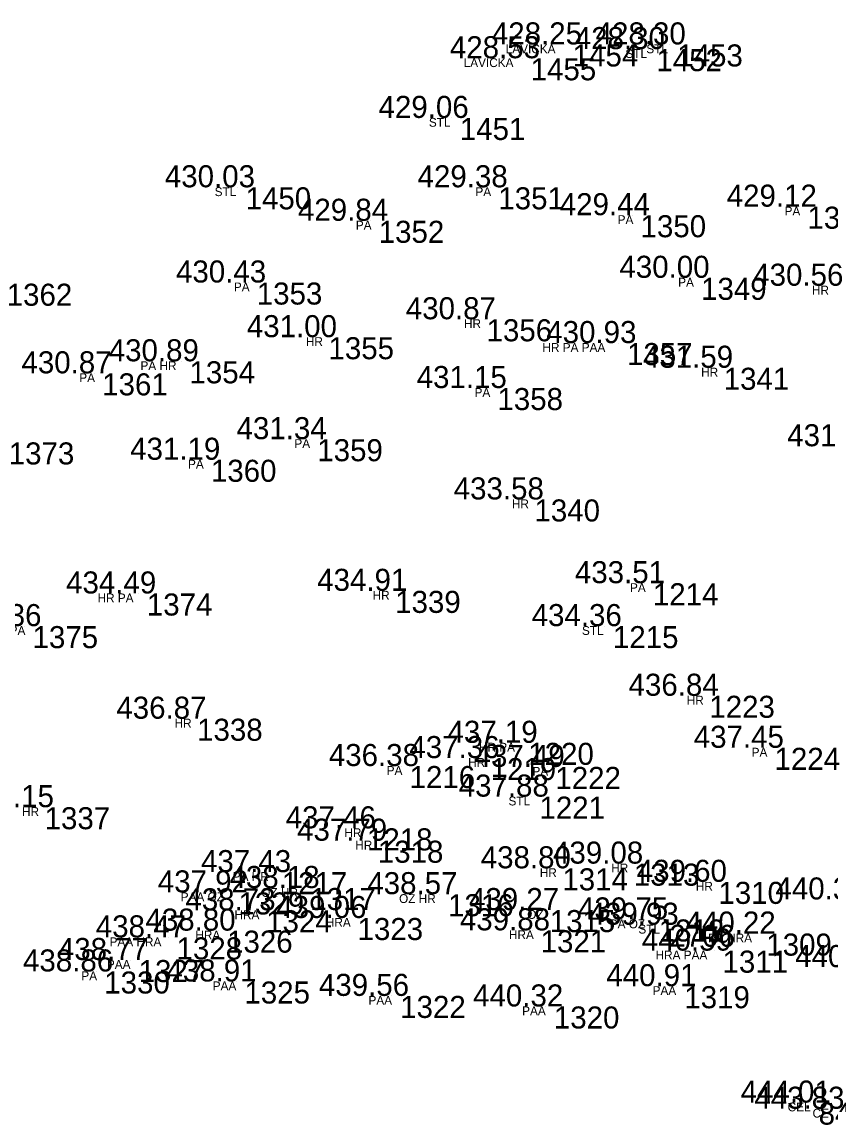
# Model space of a CAD drawing. Extents: x -639390 to -639075, y -1138747 to -1138358.
# Drawn here: x -639263.88 to -639236.35, y -1138641.21 to -1138603.69 of the extents above; entities that cross this region are included whole.
import ezdxf

# ---------------------------------------------------------------- set-up
doc = ezdxf.new("R2010")
doc.units = 0
for name, color, linetype in [('Vrstva 11', 7, 'Continuous'), ('Vrstva 12', 7, 'Continuous'), ('Vrstva 13', 7, 'Continuous'), ('Vrstva 57', 7, 'Continuous')]:
    doc.layers.add(name, color=color, linetype=linetype)

msp = doc.modelspace()

# ---------------------------------------------------------------- linework, layer by layer
at = {"layer": 'Vrstva 11'}
for p, q in [((-639245.42, -1138604.45), (-639245.42, -1138604.45)), ((-639242.57, -1138604.61), (-639242.57, -1138604.61)), ((-639241.86, -1138604.45), (-639241.86, -1138604.45)), ((-639246.85, -1138604.92), (-639246.85, -1138604.92)), ((-639249.26, -1138606.95), (-639249.26, -1138606.95)), ((-639256.55, -1138609.31), (-639256.55, -1138609.31)), ((-639247.95, -1138609.31), (-639247.95, -1138609.31)), ((-639237.43, -1138609.97), (-639237.43, -1138609.97)), ((-639252.02, -1138610.45), (-639252.02, -1138610.45)), ((-639243.11, -1138610.26), (-639243.11, -1138610.26)), ((-639241.05, -1138612.39), (-639241.05, -1138612.39)), ((-639256.17, -1138612.55), (-639256.17, -1138612.55)), ((-639236.51, -1138612.66), (-639236.51, -1138612.66)), ((-639248.35, -1138613.8), (-639248.35, -1138613.8)), ((-639253.73, -1138614.41), (-639253.73, -1138614.41)), ((-639243.57, -1138614.61), (-639243.57, -1138614.61)), ((-639258.46, -1138615.23), (-639258.46, -1138615.23)), ((-639240.28, -1138615.45), (-639240.28, -1138615.45)), ((-639261.43, -1138615.64), (-639261.43, -1138615.64)), ((-639247.98, -1138616.14), (-639247.98, -1138616.14)), ((-639254.11, -1138617.88), (-639254.11, -1138617.88)), ((-639257.73, -1138618.58), (-639257.73, -1138618.58)), ((-639246.72, -1138619.93), (-639246.72, -1138619.93)), ((-639242.69, -1138622.78), (-639242.69, -1138622.78)), ((-639259.91, -1138623.13), (-639259.91, -1138623.13)), ((-639251.46, -1138623.04), (-639251.46, -1138623.04)), ((-639263.8, -1138624.24), (-639263.8, -1138624.24)), ((-639244.05, -1138624.24), (-639244.05, -1138624.24)), ((-639240.77, -1138626.61), (-639240.77, -1138626.61)), ((-639258.2, -1138627.39), (-639258.2, -1138627.39)), ((-639246.93, -1138628.21), (-639246.93, -1138628.21)), ((-639238.55, -1138628.38), (-639238.55, -1138628.38)), ((-639250.97, -1138629), (-639250.97, -1138629)), ((-639248.21, -1138628.73), (-639248.21, -1138628.73)), ((-639246.01, -1138629.03), (-639246.01, -1138629.03)), ((-639246.55, -1138630.04), (-639246.55, -1138630.04)), ((-639263.39, -1138630.4), (-639263.39, -1138630.4)), ((-639252.42, -1138631.12), (-639252.42, -1138631.12)), ((-639252.05, -1138631.54), (-639252.05, -1138631.54)), ((-639243.34, -1138632.32), (-639243.34, -1138632.32)), ((-639255.32, -1138632.61), (-639255.32, -1138632.61)), ((-639245.77, -1138632.48), (-639245.77, -1138632.48)), ((-639240.46, -1138632.94), (-639240.46, -1138632.94)), ((-639256.79, -1138633.3), (-639256.79, -1138633.3)), ((-639254.35, -1138633.15), (-639254.35, -1138633.15)), ((-639249.66, -1138633.36), (-639249.66, -1138633.36)), ((-639255.85, -1138633.91), (-639255.85, -1138633.91)), ((-639252.74, -1138634.17), (-639252.74, -1138634.17)), ((-639246.2, -1138633.9), (-639246.2, -1138633.9)), ((-639242.49, -1138634.22), (-639242.49, -1138634.22)), ((-639257.18, -1138634.6), (-639257.18, -1138634.6)), ((-639246.51, -1138634.59), (-639246.51, -1138634.59)), ((-639242.13, -1138634.4), (-639242.13, -1138634.4)), ((-639258.9, -1138634.83), (-639258.9, -1138634.83)), ((-639238.83, -1138634.7), (-639238.83, -1138634.7)), ((-639240.32, -1138635.28), (-639240.32, -1138635.28)), ((-639260.19, -1138635.6), (-639260.19, -1138635.6)), ((-639261.36, -1138635.99), (-639261.36, -1138635.99)), ((-639256.59, -1138636.33), (-639256.59, -1138636.33)), ((-639241.62, -1138636.49), (-639241.62, -1138636.49)), ((-639251.29, -1138636.82), (-639251.29, -1138636.82)), ((-639246.06, -1138637.18), (-639246.06, -1138637.18)), ((-639237.05, -1138640.45), (-639237.05, -1138640.45)), ((-639236.49, -1138640.66), (-639236.49, -1138640.66))]:
    msp.add_line(p, q, dxfattribs=at)

# ---------------------------------------------------------------- texts
at = {"layer": 'Vrstva 12'}
for s, p in [('428.25 ', (-639247.89, -1138604.45)), ('428.30 ', (-639245.069, -1138604.61)), ('428.30 ', (-639244.359, -1138604.45)), ('428.53 ', (-639249.319, -1138604.92)), ('429.06 ', (-639251.746, -1138606.95)), ('430.03 ', (-639259.019, -1138609.31)), ('429.38 ', (-639250.419, -1138609.31)), ('429.44 ', (-639245.579, -1138610.26)), ('429.12 ', (-639239.899, -1138609.97)), ('429.84 ', (-639254.489, -1138610.45)), ('430.00 ', (-639243.549, -1138612.39)), ('430.43 ', (-639258.639, -1138612.55)), ('430.56 ', (-639238.996, -1138612.66)), ('430.87 ', (-639250.819, -1138613.8)), ('431.00 ', (-639256.229, -1138614.41)), ('430.93 ', (-639246.039, -1138614.61)), ('430.89 ', (-639260.929, -1138615.23)), ('431.59 ', (-639242.749, -1138615.45)), ('430.87 ', (-639263.899, -1138615.64)), ('431.15 ', (-639250.45, -1138616.14)), ('431.34 ', (-639256.579, -1138617.88)), ('431.48 ', (-639237.839, -1138618.12)), ('431.19 ', (-639260.199, -1138618.58)), ('433.58 ', (-639249.189, -1138619.93)), ('433.51 ', (-639245.065, -1138622.78)), ('434.49 ', (-639262.379, -1138623.13)), ('434.91 ', (-639253.835, -1138623.04)), ('434.36 ', (-639266.286, -1138624.24)), ('434.36 ', (-639246.536, -1138624.24)), ('436.84 ', (-639243.239, -1138626.61)), ('436.87 ', (-639260.669, -1138627.39)), ('437.19 ', (-639249.399, -1138628.21)), ('437.45 ', (-639241.02, -1138628.38)), ('436.38 ', (-639253.439, -1138629)), ('437.36 ', (-639250.696, -1138628.73)), ('437.49 ', (-639248.479, -1138629.03)), ('437.88 ', (-639249.019, -1138630.04)), ('438.15 ', (-639265.86, -1138630.4)), ('437.46 ', (-639254.906, -1138631.12)), ('437.79 ', (-639254.519, -1138631.54)), ('439.08 ', (-639245.809, -1138632.32)), ('437.43 ', (-639257.789, -1138632.61)), ('438.80 ', (-639248.269, -1138632.48)), ('438.18 ', (-639256.819, -1138633.15)), ('439.60 ', (-639242.959, -1138632.94)), ('437.92 ', (-639259.259, -1138633.3)), ('438.57 ', (-639252.129, -1138633.36)), ('439.27 ', (-639248.669, -1138633.9)), ('440.33 ', (-639238.239, -1138633.54)), ('438.73 ', (-639258.319, -1138633.91)), ('439.06 ', (-639255.226, -1138634.17)), ('439.75 ', (-639244.96, -1138634.22)), ('438.80 ', (-639259.679, -1138634.6)), ('439.88 ', (-639248.979, -1138634.59)), ('439.93 ', (-639244.599, -1138634.4)), ('438.47 ', (-639261.369, -1138634.83)), ('440.22 ', (-639241.299, -1138634.7)), ('440.59 ', (-639242.789, -1138635.28)), ('438.77 ', (-639262.659, -1138635.6)), ('438.86 ', (-639263.846, -1138635.99)), ('440.94 ', (-639237.569, -1138635.84)), ('438.91 ', (-639258.965, -1138636.33)), ('440.91 ', (-639243.995, -1138636.49)), ('439.56 ', (-639253.776, -1138636.82)), ('440.32 ', (-639248.529, -1138637.18)), ('444.01 ', (-639239.425, -1138640.45)), ('443.83 ', (-639238.959, -1138640.66))]:
    msp.add_text(s, height=0.75, dxfattribs=at).set_placement(p)
at = {"layer": 'Vrstva 13'}
for s, p in [(' 1454', (-639245.42, -1138605.2)), (' 1452', (-639242.57, -1138605.36)), (' 1453', (-639241.86, -1138605.2)), (' 1455', (-639246.85, -1138605.67)), (' 1451', (-639249.26, -1138607.7)), (' 1450', (-639256.55, -1138610.06)), (' 1351', (-639247.95, -1138610.06)), (' 1350', (-639243.11, -1138611.01)), (' 1348', (-639237.43, -1138610.72)), (' 1352', (-639252.02, -1138611.2)), (' 1349', (-639241.05, -1138613.14)), (' 1362', (-639264.68, -1138613.34)), (' 1353', (-639256.17, -1138613.3)), (' 1356', (-639248.35, -1138614.55)), (' 1355', (-639253.73, -1138615.16)), (' 1357', (-639243.57, -1138615.36)), (' 1354', (-639258.46, -1138615.98)), (' 1341', (-639240.28, -1138616.2)), (' 1361', (-639261.43, -1138616.39)), (' 1358', (-639247.98, -1138616.89)), (' 1373', (-639264.61, -1138618.74)), (' 1359', (-639254.11, -1138618.63)), (' 1360', (-639257.73, -1138619.33)), (' 1340', (-639246.72, -1138620.68)), (' 1214', (-639242.69, -1138623.53)), (' 1374', (-639259.91, -1138623.88)), (' 1339', (-639251.46, -1138623.79)), (' 1375', (-639263.8, -1138624.99)), (' 1215', (-639244.05, -1138624.99)), (' 1223', (-639240.77, -1138627.36)), (' 1338', (-639258.2, -1138628.14)), (' 1220', (-639246.93, -1138628.96)), (' 1224', (-639238.55, -1138629.13)), (' 1216', (-639250.97, -1138629.75)), (' 1219', (-639248.21, -1138629.48)), (' 1222', (-639246.01, -1138629.78)), (' 1221', (-639246.55, -1138630.79)), (' 1337', (-639263.39, -1138631.15)), (' 1218', (-639252.42, -1138631.87)), (' 1318', (-639252.05, -1138632.29)), (' 1313', (-639243.34, -1138633.07)), (' 1217', (-639255.32, -1138633.36)), (' 1314', (-639245.77, -1138633.23)), (' 1317', (-639254.35, -1138633.9)), (' 1310', (-639240.46, -1138633.69)), (' 1329', (-639256.79, -1138634.05)), (' 1316', (-639249.66, -1138634.11)), (' 1315', (-639246.2, -1138634.65)), (' 1324', (-639255.85, -1138634.66)), (' 1323', (-639252.74, -1138634.92)), (' 1312', (-639242.49, -1138634.97)), (' 1326', (-639257.18, -1138635.35)), (' 1321', (-639246.51, -1138635.34)), (' 2706', (-639242.13, -1138635.15)), (' 1328', (-639258.9, -1138635.58)), (' 1309', (-639238.83, -1138635.45)), (' 1311', (-639240.32, -1138636.03)), (' 1327', (-639260.19, -1138636.35)), (' 1330', (-639261.36, -1138636.74)), (' 1325', (-639256.59, -1138637.08)), (' 1319', (-639241.62, -1138637.24)), (' 1322', (-639251.29, -1138637.57)), (' 1320', (-639246.06, -1138637.93)), (' 84', (-639237.05, -1138641.2))]:
    msp.add_text(s, height=0.75, dxfattribs=at).set_placement(p)
at = {"layer": 'Vrstva 57'}
for s, p in [('LAVICKA', (-639247.42, -1138604.75)), ('STL', (-639243.345, -1138604.91)), ('STL', (-639242.635, -1138604.75)), ('LAVICKA', (-639248.85, -1138605.22)), ('STL', (-639250.035, -1138607.25)), ('STL', (-639257.325, -1138609.61)), ('PA', (-639248.45, -1138609.61)), ('PA', (-639237.93, -1138610.27)), ('PA', (-639252.52, -1138610.75)), ('PA', (-639243.61, -1138610.56)), ('PA', (-639241.55, -1138612.69)), ('PA', (-639256.67, -1138612.85)), ('HR', (-639236.999, -1138612.96)), ('HR', (-639248.839, -1138614.1)), ('HR', (-639254.219, -1138614.71)), ('HR PA PAA', (-639246.17, -1138614.91)), ('PA HR', (-639259.849, -1138615.53)), ('HR', (-639240.769, -1138615.75)), ('PA', (-639261.93, -1138615.94)), ('PA', (-639248.48, -1138616.44)), ('PA', (-639254.61, -1138618.18)), ('PA', (-639258.23, -1138618.88)), ('HR', (-639247.209, -1138620.23)), ('PA', (-639243.19, -1138623.08)), ('HR PA', (-639261.31, -1138623.43)), ('HR', (-639251.949, -1138623.34)), ('PA', (-639264.3, -1138624.54)), ('STL', (-639244.825, -1138624.54)), ('HR', (-639241.259, -1138626.91)), ('HR', (-639258.689, -1138627.69)), ('HR PA', (-639248.33, -1138628.51)), ('PA', (-639239.05, -1138628.68)), ('PA', (-639251.47, -1138629.3)), ('HR', (-639248.699, -1138629.03)), ('PA', (-639246.51, -1138629.33)), ('STL', (-639247.325, -1138630.34)), ('HR', (-639263.879, -1138630.7)), ('HR', (-639252.909, -1138631.42)), ('HR', (-639252.539, -1138631.84)), ('HR', (-639243.829, -1138632.62)), ('PA HR', (-639256.709, -1138632.91)), ('HR', (-639246.259, -1138632.78)), ('HR', (-639240.949, -1138633.24)), ('PAA OZ', (-639258.479, -1138633.6)), ('OZ HR', (-639255.739, -1138633.45)), ('OZ HR', (-639251.049, -1138633.66)), ('HRA', (-639256.65, -1138634.21)), ('HRA', (-639253.54, -1138634.47)), ('OZ', (-639246.689, -1138634.2)), ('PA OZ', (-639243.879, -1138634.52)), ('HRA', (-639257.98, -1138634.9)), ('HRA', (-639247.31, -1138634.89)), ('STL', (-639242.905, -1138634.7)), ('PAA HRA', (-639260.9, -1138635.13)), ('PA HRA', (-639240.53, -1138635)), ('HRA PAA', (-639242.32, -1138635.58)), ('PAA', (-639260.99, -1138635.9)), ('PA', (-639261.86, -1138636.29)), ('PAA', (-639257.39, -1138636.63)), ('PAA', (-639242.42, -1138636.79)), ('PAA', (-639252.09, -1138637.12)), ('PAA', (-639246.86, -1138637.48)), ('CEL', (-639237.825, -1138640.75)), ('CE', (-639236.978, -1138640.96))]:
    msp.add_text(s, height=0.3, dxfattribs=at).set_placement(p)

doc.saveas('drawing.dxf')
